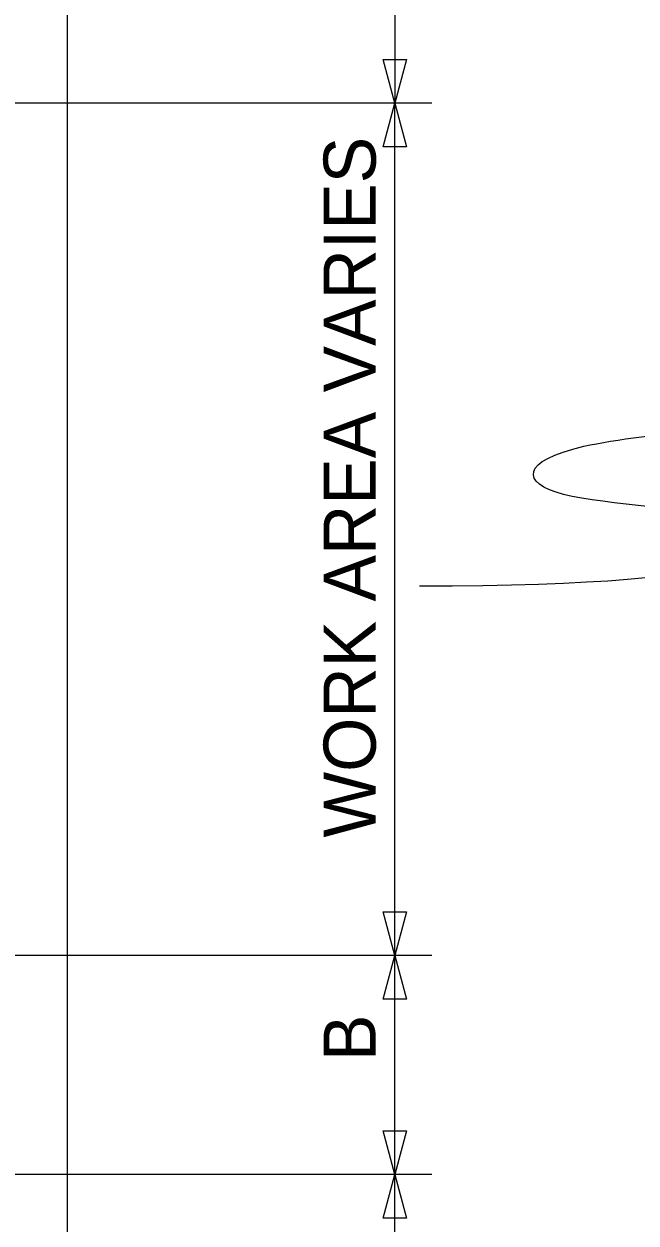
# Model space of a CAD drawing. Extents: x 16744 to 19504, y 5731 to 6974.
# Drawn here: x 18055.7 to 18137.9, y 6552.5 to 6713.6 of the extents above; entities that cross this region are included whole.
import ezdxf

# ---------------------------------------------------------------- set-up
doc = ezdxf.new("R2010")
doc.units = 0
doc.layers.add('PAVT_EDGE_EX', color=7, linetype='Continuous')
doc.layers.add('TYPICAL_TEXT_DIMEN_PR', color=7, linetype='Continuous')

msp = doc.modelspace()

# ---------------------------------------------------------------- linework, layer by layer
at = {"layer": 'PAVT_EDGE_EX'}
msp.add_line((18061.5, 6891.16), (18061.5, 6061.98), dxfattribs=at)
at = {"layer": 'TYPICAL_TEXT_DIMEN_PR'}
for p, q in [((18105.5, 6752.97), (18105.5, 6702.97)), ((18105.5, 6702.97), (18103.93, 6708.83)), ((18103.93, 6708.83), (18105.5, 6708.83)), ((18105.5, 6708.83), (18107.07, 6708.83)), ((18107.07, 6708.83), (18105.5, 6702.97)), ((18110.5, 6702.97), (18028.11, 6702.97)), ((18103.93, 6697.11), (18105.5, 6702.97)), ((18105.5, 6588.44), (18105.5, 6702.97)), ((18105.5, 6702.97), (18107.07, 6697.11)), ((18105.5, 6697.11), (18103.93, 6697.11)), ((18107.07, 6697.11), (18105.5, 6697.11)), ((18105.5, 6588.44), (18103.93, 6594.3)), ((18103.93, 6594.3), (18105.5, 6594.3)), ((18105.5, 6594.3), (18107.07, 6594.3)), ((18107.07, 6594.3), (18105.5, 6588.44)), ((18110.5, 6588.44), (18028.11, 6588.44)), ((18103.93, 6582.57), (18105.5, 6588.44)), ((18105.5, 6559.01), (18105.5, 6588.44)), ((18105.5, 6588.44), (18107.07, 6582.57)), ((18105.5, 6582.57), (18103.93, 6582.57)), ((18107.07, 6582.57), (18105.5, 6582.57)), ((18105.5, 6559.01), (18103.93, 6564.87)), ((18103.93, 6564.87), (18105.5, 6564.87)), ((18105.5, 6564.87), (18107.07, 6564.87)), ((18107.07, 6564.87), (18105.5, 6559.01)), ((18110.5, 6559.01), (18028.11, 6559.01)), ((18103.93, 6553.15), (18105.5, 6559.01)), ((18105.5, 6528.44), (18105.5, 6559.01)), ((18105.5, 6559.01), (18107.07, 6553.15)), ((18105.5, 6553.15), (18103.93, 6553.15)), ((18107.07, 6553.15), (18105.5, 6553.15))]:
    msp.add_line(p, q, dxfattribs=at)
msp.add_open_spline([(18108.81, 6638.12), (18157.28, 6638.12), (18157.28, 6648.88), (18122.36, 6648.88), (18122.36, 6657.93), (18156.57, 6659.69), (18164.86, 6659.98)], degree=3, dxfattribs=at)

# ---------------------------------------------------------------- texts
for s, p in [('WORK AREA VARIES', (18102.94, 6604.29)), ('B', (18102.94, 6574.27))]:
    msp.add_text(s, height=7, rotation=90, dxfattribs=at).set_placement(p)

doc.saveas('drawing.dxf')
